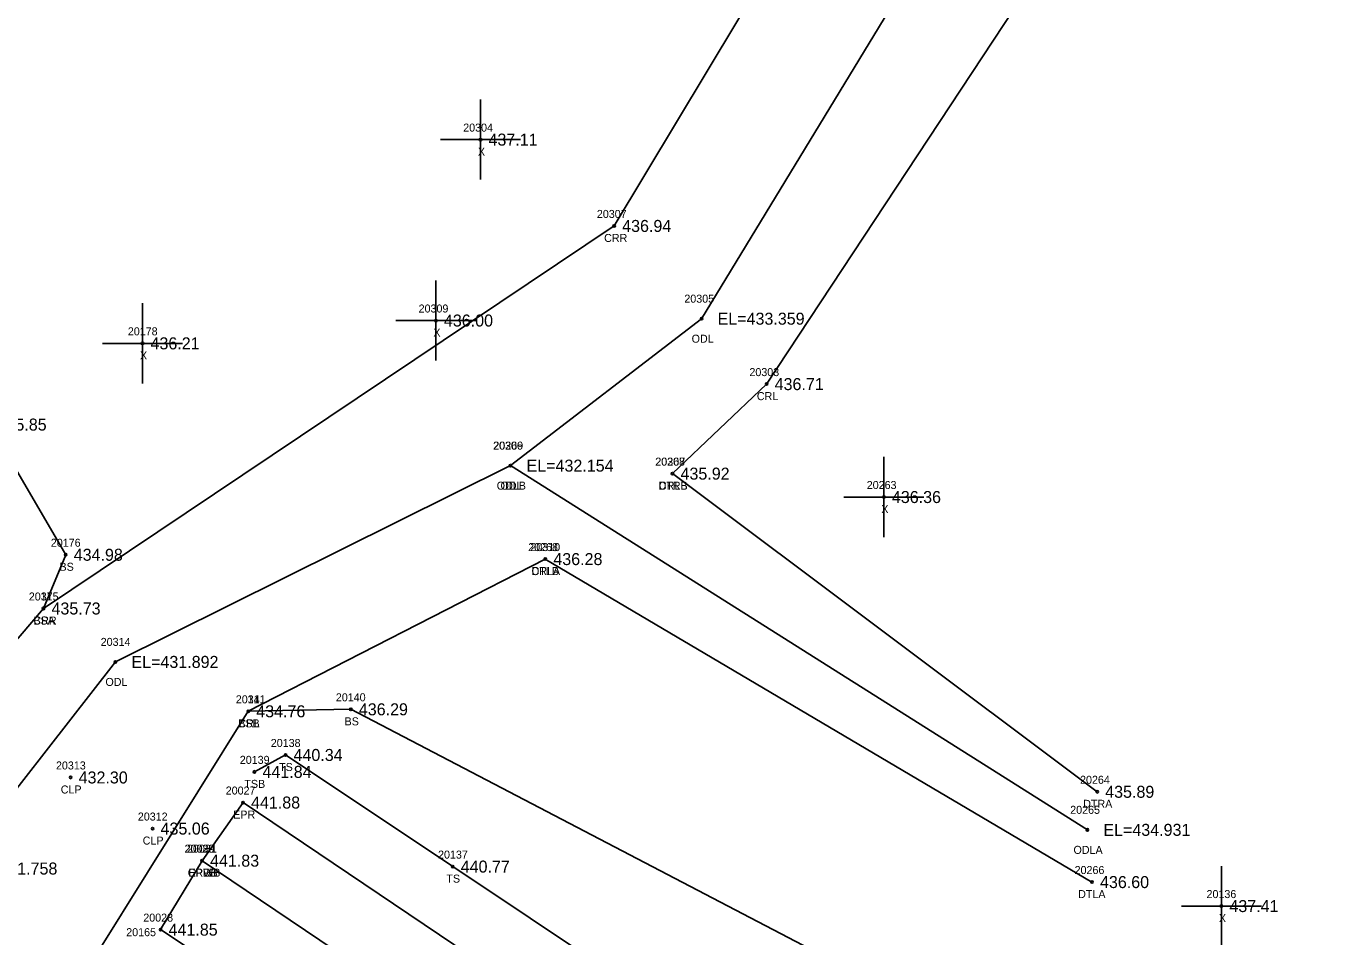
# Model space of a CAD drawing. Extents: x 1797709 to 1799052, y 896018 to 896955.
# Drawn here: x 1798378.7 to 1798542.7, y 896463 to 896576.7 of the extents above; entities that cross this region are included whole.
import ezdxf

# ---------------------------------------------------------------- set-up
doc = ezdxf.new("R2010")
doc.units = 0
for name, color, linetype in [('RD_DTM_BkLn1', 7, 'Continuous'), ('RD_DTM_BkLn2', 7, 'Continuous'), ('RD_DTM_BkLn_txCode', 7, 'Continuous'), ('RD_EX_H2O', 7, 'Continuous'), ('RD_EX_H2O_txCode', 7, 'Continuous'), ('RD_EX_Misc', 7, 'Continuous'), ('RD_EX_Misc_txCode', 7, 'Continuous'), ('RD_EX_Road', 7, 'Continuous'), ('RD_EX_Road_txCode', 7, 'Continuous'), ('RD_EX_TX_H2O_ELEV', 7, 'Continuous'), ('RD_EX_TX_Misc_ELEV', 7, 'Continuous'), ('RD_EX_TX_Road_ELEV', 7, 'Continuous'), ('RD_HC_Survey_ELEV', 7, 'Continuous'), ('RD_HC_Survey_txCode', 7, 'Continuous'), ('RD_SMD_Locator', 7, 'Continuous')]:
    doc.layers.add(name, color=color, linetype=linetype)

msp = doc.modelspace()

# ---------------------------------------------------------------- linework, layer by layer
at = {"layer": 'RD_DTM_BkLn1'}
msp.add_lwpolyline([(1799011.08, 896069.91), (1798925.85, 896126.62), (1798837.59, 896184.3), (1798748.15, 896241.48), (1798659.28, 896299.6), (1798569.04, 896359.56), (1798481.49, 896418.06), (1798400.67, 896472.53)], dxfattribs=at)
at = {"layer": 'RD_DTM_BkLn2'}
for points in [[(1798380.86, 896504.02), (1798383.64, 896510.73), (1798374.12, 896526.99), (1798314.49, 896563.64)], [(1798779.67, 896245.03), (1798759.32, 896261.95), (1798678.07, 896324.5), (1798585.68, 896384.49), (1798503.1, 896447.71), (1798419.26, 896491.43), (1798406.44, 896491.18)], [(1799018.13, 896081.6), (1798933.54, 896137.5), (1798843.36, 896196.36), (1798754.6, 896254.77), (1798666.48, 896312.08), (1798576.97, 896371.21), (1798490.12, 896433.01), (1798431.99, 896471.79), (1798411.1, 896485.73), (1798407.22, 896483.62)]]:
    msp.add_lwpolyline(points, dxfattribs=at)
at = {"layer": 'RD_EX_H2O'}
for p, q in [((1798511.28, 896476.38), (1798439.21, 896521.86)), ((1798512.51, 896481.13), (1798459.45, 896520.86)), ((1798511.86, 896469.86), (1798443.56, 896510.19))]:
    msp.add_line(p, q, dxfattribs=at)
for points in [[(1798652.43, 896917.58), (1798601.94, 896827.15), (1798558.78, 896718.92), (1798516.66, 896628.32), (1798463.08, 896540.21), (1798439.21, 896521.86), (1798389.85, 896497.35), (1798369.72, 896471.55), (1798343.52, 896433.35), (1798291.39, 896374.31), (1798235.39, 896326.89), (1798184.99, 896269.63), (1798095.18, 896198.01), (1798023.89, 896139.85)], [(1798663.68, 896911.94), (1798617.01, 896821.94), (1798571.81, 896720.45), (1798529.2, 896619.95), (1798471.21, 896532.04), (1798459.45, 896520.86)], [(1798502.61, 896635.66), (1798452.16, 896551.79), (1798380.86, 896504.02), (1798360.17, 896479.84), (1798335.44, 896438.68), (1798277.37, 896387.2), (1798228.36, 896339.61), (1798175.66, 896278.7), (1798083.83, 896204.11), (1798020.11, 896146.19)], [(1798443.56, 896510.19), (1798406.44, 896491.18), (1798387.57, 896460.96), (1798358.05, 896423.51), (1798298.17, 896368.97), (1798249.86, 896318.72)]]:
    msp.add_lwpolyline(points, dxfattribs=at)
at = {"layer": 'RD_EX_Misc'}
for p, q in [((1798435.46, 896557.57), (1798435.46, 896567.57)), ((1798430.46, 896562.57), (1798440.46, 896562.57)), ((1798429.89, 896534.98), (1798429.89, 896544.98)), ((1798393.23, 896532.13), (1798393.23, 896542.13)), ((1798424.89, 896539.98), (1798434.89, 896539.98)), ((1798388.23, 896537.13), (1798398.23, 896537.13)), ((1798485.86, 896512.94), (1798485.86, 896522.94)), ((1798480.86, 896517.94), (1798490.86, 896517.94)), ((1798528.03, 896461.86), (1798528.03, 896471.86)), ((1798523.03, 896466.86), (1798533.03, 896466.86))]:
    msp.add_line(p, q, dxfattribs=at)
at = {"layer": 'RD_EX_Road'}
for points in [[(1799016.83, 896078.37), (1798931.94, 896134.3), (1798843.73, 896191.67), (1798753.3, 896249.87), (1798664.51, 896307.9), (1798573.47, 896367.69), (1798486.82, 896425.22), (1798405.79, 896479.79), (1798400.67, 896472.53)], [(1799005.77, 896063.27), (1798987.67, 896075.09), (1798974.89, 896083.47), (1798920.67, 896119.42), (1798834.47, 896175.11), (1798832.16, 896176.64), (1798822.63, 896182.83), (1798742.86, 896234.39), (1798653.4, 896292.37), (1798563.64, 896351.71), (1798476.02, 896410.61), (1798395.49, 896463.92), (1798400.67, 896472.53)]]:
    msp.add_lwpolyline(points, dxfattribs=at)
at = {"layer": 'RD_SMD_Locator'}
for centre in [(1798435.46, 896562.57), (1798452.16, 896551.79), (1798463.08, 896540.21), (1798429.89, 896539.98), (1798393.23, 896537.13), (1798471.21, 896532.04), (1798439.21, 896521.86), (1798439.21, 896521.86), (1798459.45, 896520.86), (1798459.45, 896520.86), (1798485.86, 896517.94), (1798383.64, 896510.73), (1798443.56, 896510.19), (1798443.56, 896510.19), (1798380.86, 896504.02), (1798380.86, 896504.02), (1798389.85, 896497.35), (1798406.44, 896491.18), (1798406.44, 896491.18), (1798419.26, 896491.43), (1798411.1, 896485.73), (1798384.25, 896482.92), (1798407.22, 896483.62), (1798512.51, 896481.13), (1798405.79, 896479.79), (1798394.49, 896476.54), (1798511.28, 896476.38), (1798400.67, 896472.53), (1798400.67, 896472.53), (1798400.67, 896472.53), (1798431.99, 896471.79), (1798511.86, 896469.86), (1798528.03, 896466.86), (1798395.49, 896463.92)]:
    msp.add_circle(centre, 0.15, dxfattribs=at)

# ---------------------------------------------------------------- texts
at = {"layer": 'RD_DTM_BkLn_txCode'}
for s, p in [('20176', (1798381.78, 896511.73)), ('BS', (1798382.86, 896508.73)), ('20175', (1798379.03, 896505.02)), ('BSA', (1798379.6, 896502.02)), ('20141', (1798404.89, 896492.18)), ('20140', (1798417.39, 896492.43)), ('BSB', (1798405.19, 896489.18)), ('BS', (1798418.48, 896489.43)), ('20138', (1798409.26, 896486.73)), ('20139', (1798405.39, 896484.62)), ('TS', (1798410.3, 896483.73)), ('TSB', (1798405.96, 896481.62)), ('20137', (1798430.16, 896472.79)), ('TS', (1798431.2, 896469.79)), ('20165', (1798391.2, 896463.1))]:
    msp.add_text(s, height=1, dxfattribs=at).set_placement(p)
at = {"layer": 'RD_EX_H2O_txCode'}
for s, p in [('20307', (1798450, 896552.79)), ('CRR', (1798450.91, 896549.79)), ('20305', (1798460.93, 896542.21)), ('ODL', (1798461.84, 896537.21)), ('20303', (1798469.06, 896533.04)), ('CRL', (1798469.99, 896530.04)), ('20306', (1798437.03, 896523.86)), ('20269', (1798437.07, 896523.86)), ('20308', (1798457.29, 896521.86)), ('20267', (1798457.31, 896521.86)), ('ODLB', (1798437.49, 896518.86)), ('ODL', (1798437.96, 896518.86)), ('CRLB', (1798457.75, 896518.86)), ('DTRB', (1798457.71, 896518.86)), ('20268', (1798441.42, 896511.19)), ('20310', (1798441.69, 896511.19)), ('CRLA', (1798441.84, 896508.19)), ('DTLB', (1798441.84, 896508.19)), ('20315', (1798379.03, 896505.02)), ('CRR', (1798379.61, 896502.02)), ('20314', (1798388.01, 896499.35)), ('ODL', (1798388.6, 896494.35)), ('20311', (1798404.89, 896492.18)), ('CRL', (1798405.21, 896489.18)), ('20264', (1798510.37, 896482.13)), ('DTRA', (1798510.76, 896479.13)), ('20265', (1798509.14, 896478.38)), ('ODLA', (1798509.55, 896473.38)), ('20266', (1798509.69, 896470.86)), ('DTLA', (1798510.13, 896467.86))]:
    msp.add_text(s, height=1, dxfattribs=at).set_placement(p)
at = {"layer": 'RD_EX_Misc_txCode'}
for s, p in [('20304', (1798433.3, 896563.57)), ('X', (1798435.14, 896560.57)), ('20309', (1798427.73, 896540.98)), ('20178', (1798391.4, 896538.13)), ('X', (1798429.57, 896537.98)), ('X', (1798392.92, 896535.13)), ('20263', (1798483.72, 896518.94)), ('X', (1798485.54, 896515.94)), ('20136', (1798526.17, 896467.86)), ('X', (1798527.72, 896464.86))]:
    msp.add_text(s, height=1, dxfattribs=at).set_placement(p)
at = {"layer": 'RD_EX_Road_txCode'}
for s, p in [('20027', (1798403.63, 896480.79)), ('EPR', (1798404.56, 896477.79)), ('20030', (1798398.48, 896473.53)), ('20029', (1798398.51, 896473.53)), ('EPRB', (1798398.97, 896470.53)), ('EPLB', (1798398.99, 896470.53)), ('20028', (1798393.33, 896464.92))]:
    msp.add_text(s, height=1, dxfattribs=at).set_placement(p)
at = {"layer": 'RD_EX_TX_H2O_ELEV'}
for s, p in [('436.94', (1798453.16, 896551.04)), ('EL=433.359', (1798465.08, 896539.46)), ('436.71', (1798472.21, 896531.29)), ('EL=432.154', (1798441.21, 896521.11)), ('EL=432.154', (1798441.21, 896521.11)), ('435.92', (1798460.45, 896520.11)), ('435.92', (1798460.45, 896520.11)), ('436.28', (1798444.56, 896509.44)), ('436.28', (1798444.56, 896509.44)), ('435.73', (1798381.86, 896503.27)), ('EL=431.892', (1798391.85, 896496.6)), ('434.76', (1798407.44, 896490.43)), ('435.89', (1798513.51, 896480.38)), ('EL=434.931', (1798513.28, 896475.63)), ('EL=431.758', (1798371.72, 896470.8)), ('436.60', (1798512.86, 896469.11))]:
    msp.add_text(s, height=1.5, dxfattribs=at).set_placement(p)
at = {"layer": 'RD_EX_TX_Misc_ELEV'}
for s, p in [('437.11', (1798436.46, 896561.82)), ('436.00', (1798430.89, 896539.23)), ('436.21', (1798394.23, 896536.38)), ('435.85', (1798375.12, 896526.24)), ('436.36', (1798486.86, 896517.19)), ('434.98', (1798384.64, 896509.98)), ('435.73', (1798381.86, 896503.27)), ('434.76', (1798407.44, 896490.43)), ('436.29', (1798420.26, 896490.68)), ('440.34', (1798412.1, 896484.98)), ('441.84', (1798408.22, 896482.87)), ('440.77', (1798432.99, 896471.04)), ('437.41', (1798529.03, 896466.11))]:
    msp.add_text(s, height=1.5, dxfattribs=at).set_placement(p)
at = {"layer": 'RD_EX_TX_Road_ELEV'}
for s, p in [('441.88', (1798406.79, 896479.04)), ('441.83', (1798401.67, 896471.78)), ('441.83', (1798401.67, 896471.78)), ('441.85', (1798396.49, 896463.17))]:
    msp.add_text(s, height=1.5, dxfattribs=at).set_placement(p)
at = {"layer": 'RD_HC_Survey_ELEV'}
for s, p in [('432.30', (1798385.25, 896482.17)), ('435.06', (1798395.49, 896475.79)), ('441.83', (1798401.67, 896471.78))]:
    msp.add_text(s, height=1.5, dxfattribs=at).set_placement(p)
at = {"layer": 'RD_HC_Survey_txCode'}
for s, p in [('20313', (1798382.42, 896483.92)), ('CLP', (1798383.02, 896480.92)), ('20312', (1798392.65, 896477.54)), ('CLP', (1798393.26, 896474.54)), ('20031', (1798398.8, 896473.53)), ('CRWB', (1798398.88, 896470.53))]:
    msp.add_text(s, height=1, dxfattribs=at).set_placement(p)

doc.saveas('drawing.dxf')
